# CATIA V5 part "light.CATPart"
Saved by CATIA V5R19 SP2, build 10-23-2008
Part number: light
Bounding box of the stored display mesh (mm): x -1262.069 to 1831.329, y -627.021 to 627.021, z 337.524 to 677.907
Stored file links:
  C:\BEHROOZ\catia learning\tarh haye mashin\hb\light.CATPart
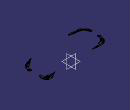
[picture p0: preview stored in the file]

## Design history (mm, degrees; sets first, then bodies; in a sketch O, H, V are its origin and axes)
Set1 "light"
  Fill1: Boundary ({fillboundary BoundaryWire DatumCurve1}; {fillboundary BoundaryWire DatumCurve2}; DatumCurve3; Circle1; DatumCurve4; DatumCurve5)
  DatumCurve1
  DatumSurface1
  DatumCurve2
  DatumSurface2
  DatumCurve3
  Circle1: stored without definition
  DatumCurve4
  DatumCurve5
  Symmetry1: ToTransfor Fill1, Reference zx-plane
  DatumSurface3 to DatumSurface13
  ThickSurface1: Surface DatumSurface14, TopOffset 1, BotOffset 0
  DatumSurface14
  ThickSurface2: Surface DatumSurface15, TopOffset 1, BotOffset 0
  DatumSurface15
  ThickSurface3: Surface DatumSurface16, TopOffset 1, BotOffset 0
  DatumSurface16
  ThickSurface4: Surface DatumSurface17, TopOffset 1, BotOffset 0
  DatumSurface17
  ThickSurface5: Surface DatumSurface18, TopOffset 1, BotOffset 0
  DatumSurface18
  ThickSurface6: Surface DatumSurface19, TopOffset 1, BotOffset 0
  DatumSurface19 to DatumSurface30
  ThickSurface7: Surface DatumSurface29, TopOffset 1, BotOffset 0
  ThickSurface8: Surface DatumSurface28, TopOffset 1, BotOffset 0
  ThickSurface9: Surface DatumSurface27, TopOffset 1, BotOffset 0
  ThickSurface10: Surface DatumSurface10, TopOffset 1, BotOffset 0
  ThickSurface11: Surface DatumSurface11, TopOffset 1, BotOffset 0
  ThickSurface12: Surface DatumSurface12, TopOffset 1, BotOffset 0
  ThickSurface13: Surface DatumSurface4, TopOffset 1, BotOffset 0
  ThickSurface14: Surface DatumSurface5, TopOffset 1, BotOffset 0
  ThickSurface15: Surface DatumSurface6, TopOffset 1, BotOffset 0
  ThickSurface16: Surface DatumSurface7, TopOffset 1, BotOffset 0
  ThickSurface17: Surface DatumSurface8, TopOffset 1, BotOffset 0
  ThickSurface18: Surface DatumSurface22, TopOffset 1, BotOffset 0
  ThickSurface19: Surface DatumSurface23, TopOffset 1, BotOffset 0
  ThickSurface20: Surface DatumSurface24, TopOffset 1, BotOffset 0
  ThickSurface21: Surface DatumSurface25, TopOffset 1, BotOffset 0
  ThickSurface22: Surface DatumSurface21, TopOffset 1, BotOffset 0
  ThickSurface23: Surface DatumSurface32, TopOffset 1, BotOffset 0
  DatumSurface31
  DatumSurface32
  ThickSurface24: Surface DatumSurface33, TopOffset 1, BotOffset 0
  DatumSurface33 to DatumSurface40
  ThickSurface25: Surface DatumSurface35, TopOffset 1, BotOffset 0
  DatumSurface41 to DatumSurface47
  ThickSurface26: Surface DatumSurface42, TopOffset 1, BotOffset 0
  ThickSurface27: Surface DatumSurface47, TopOffset 1, BotOffset 0
  ThickSurface28: Surface DatumSurface46, TopOffset 1, BotOffset 0
  ThickSurface29: Surface DatumSurface44, TopOffset 1, BotOffset 0
  ThickSurface30: Surface DatumSurface48, TopOffset 1, BotOffset 0
  DatumSurface48
  ThickSurface31: Surface DatumSurface49, TopOffset 1, BotOffset 0
  DatumSurface49
  ThickSurface32: Surface DatumSurface36, TopOffset 1, BotOffset 0
  ThickSurface33: Surface DatumSurface37, TopOffset 1, BotOffset 0
  ThickSurface34: Surface DatumSurface39, TopOffset 1, BotOffset 0
  ThickSurface35: Surface DatumSurface40, TopOffset 1, BotOffset 0
  ThickSurface36: Surface DatumSurface50, TopOffset 1, BotOffset 0
  DatumSurface50
  ThickSurface37: Surface DatumSurface51, TopOffset 1, BotOffset 0
  DatumSurface51
Body1 (main body)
